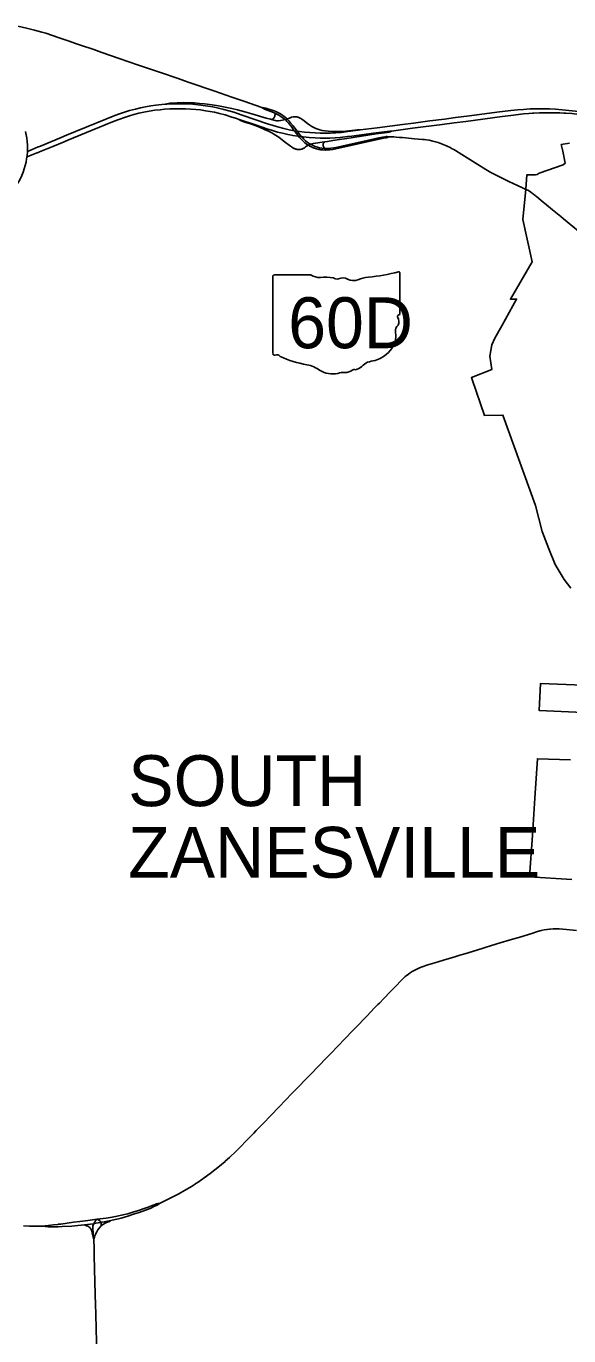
# Model space of a CAD drawing. Extents: x 2015843 to 2287843, y 623733 to 799733.
# Drawn here: x 2104493 to 2116443, y 678304 to 707117 of the extents above; entities that cross this region are included whole.
import ezdxf

# ---------------------------------------------------------------- set-up
doc = ezdxf.new("R2010")
doc.units = 0
for name, color, linetype in [('GM_X_Corporation', 7, 'Continuous'), ('GM_X_Corporation_Text', 7, 'Continuous'), ('GM_X_Interchange_Ramps', 7, 'Continuous'), ('GM_X_Interstate_Shield', 7, 'Continuous'), ('GM_X_State_Route', 7, 'Continuous'), ('GM_X_State_Shield', 7, 'Continuous'), ('GM_X_US_Route', 7, 'Continuous'), ('UT_P_Electric', 7, 'Continuous')]:
    doc.layers.add(name, color=color, linetype=linetype)

msp = doc.modelspace()

# ---------------------------------------------------------------- linework, layer by layer
at = {"layer": 'GM_X_Corporation'}
for points in [[(2116485, 694750), (2116340, 694942), (2116139, 695275), (2116001, 695619), (2115854, 695998), (2115707, 696572), (2114993, 698562), (2114585, 698555), (2114312, 699342), (2114299, 699384), (2114748, 699566), (2114702, 699857), (2114749, 700104), (2114817, 700252), (2114970, 700526), (2115293, 701114), (2115158, 701110), (2115639, 701929), (2115427, 702866), (2115498, 703530), (2115516, 703846), (2115709, 703850), (2115748, 703856), (2115791, 703880), (2116317, 704069), (2116362, 704101), (2116309, 704368), (2116276, 704512), (2116456, 704542)], [(2116759, 692016), (2115787, 692062), (2115818, 692654), (2117881, 692571)], [(2116508, 688344), (2115580, 688405), (2115645, 689311), (2115692, 690134), (2115750, 691001), (2116478, 690976)]]:
    msp.add_lwpolyline(points, dxfattribs=at)
at = {"layer": 'GM_X_Interchange_Ramps'}
for points in [[(2106137, 680715), (2106142, 680745), (2106142, 680774), (2106137, 680793), (2106134, 680800), (2106127, 680815), (2106120, 680825), (2106113, 680833), (2106106, 680841), (2106097, 680848), (2106083, 680856), (2106055, 680869)], [(2105778, 680744), (2105807, 680731), (2105822, 680727), (2105838, 680721), (2105854, 680714), (2105868, 680706), (2105882, 680696), (2105895, 680684), (2105906, 680672), (2105916, 680658), (2105924, 680643), (2105931, 680628), (2105939, 680606), (2105948, 680566), (2105981, 680412)]]:
    msp.add_lwpolyline(points, dxfattribs=at)
at = {"layer": 'GM_X_Interstate_Shield'}
msp.add_arc((2103013, 704433), 1509, 281.537, 14.1934, dxfattribs=at)
at = {"layer": 'GM_X_State_Route'}
msp.add_line((2114644, 686858), (2114694, 686874), dxfattribs=at)
for points in [[(2115340, 687070), (2115457, 687106), (2115630, 687158), (2115756, 687197), (2115836, 687219), (2115900, 687234), (2115965, 687245), (2116016, 687251)], [(2116016, 687251), (2116030, 687252), (2116096, 687257), (2116161, 687258), (2116227, 687255), (2116391, 687241), (2116538, 687226), (2116612, 687223)], [(2114694, 686874), (2114859, 686924), (2115206, 687029), (2115340, 687070)], [(2112843, 686206), (2112860, 686221), (2112911, 686262), (2112951, 686290), (2112993, 686317), (2113049, 686350), (2113108, 686379), (2113153, 686399), (2113215, 686422), (2113339, 686462), (2113496, 686511), (2113685, 686567), (2113810, 686605), (2113935, 686644), (2114045, 686676), (2114151, 686708), (2114419, 686789), (2114576, 686838), (2114644, 686858)], [(2112525, 685887), (2112529, 685891), (2112660, 686027), (2112720, 686088)], [(2112720, 686088), (2112763, 686132), (2112811, 686178), (2112843, 686206)], [(2112279, 685630), (2112364, 685720), (2112525, 685887)], [(2111164, 684479), (2111202, 684518), (2111511, 684835), (2111557, 684881), (2111646, 684978), (2111737, 685073), (2111999, 685343), (2112158, 685509), (2112239, 685590), (2112274, 685625), (2112279, 685630)], [(2110810, 684113), (2110871, 684177), (2111164, 684479)], [(2110465, 683757), (2110495, 683788), (2110643, 683941), (2110810, 684113)], [(2109558, 682818), (2109709, 682975), (2109880, 683151), (2110062, 683340), (2110347, 683635), (2110465, 683757)], [(2108878, 682144), (2108972, 682227), (2109115, 682363), (2109241, 682492), (2109310, 682562), (2109401, 682656), (2109489, 682747)], [(2109489, 682747), (2109504, 682762), (2109558, 682818)], [(2108194, 681629), (2108207, 681638), (2108303, 681701), (2108410, 681776), (2108543, 681872), (2108647, 681952), (2108749, 682035), (2108874, 682141), (2108878, 682144)], [(2107428, 681218), (2107577, 681288), (2107738, 681368), (2107854, 681429), (2107983, 681501), (2108096, 681568), (2108194, 681629)], [(2106361, 680842), (2106453, 680861), (2106524, 680878), (2106582, 680893), (2106735, 680939), (2106859, 680977), (2106983, 681019), (2107121, 681068), (2107223, 681108), (2107319, 681153), (2107362, 681171), (2107392, 681186), (2107409, 681197), (2107419, 681205), (2107428, 681218)], [(2105981, 680412), (2105970, 680546), (2105963, 680683), (2105964, 680718), (2105968, 680739), (2105974, 680757), (2105981, 680771), (2105987, 680784), (2105994, 680795), (2106003, 680808), (2106011, 680819), (2106020, 680831), (2106031, 680845), (2106055, 680869)], [(2105981, 680412), (2105991, 680452), (2105998, 680474), (2106009, 680505), (2106020, 680535), (2106033, 680566), (2106048, 680594), (2106074, 680636), (2106102, 680672), (2106137, 680715), (2106143, 680720), (2106151, 680726), (2106168, 680742), (2106195, 680761), (2106230, 680783), (2106260, 680796), (2106284, 680806), (2106328, 680820), (2106341, 680827), (2106361, 680842)], [(2106034, 678559), (2106031, 678679), (2106027, 678768), (2106025, 678810), (2106023, 678974), (2106009, 679483), (2106001, 679778), (2105994, 680064), (2105989, 680231), (2105981, 680412)], [(2105898, 675462), (2105899, 675476), (2105908, 675640), (2105914, 675738), (2105923, 675918), (2105923, 675922), (2105941, 676213), (2105943, 676250), (2105961, 676511), (2105964, 676556), (2105977, 676781), (2105995, 677092), (2106001, 677197), (2106029, 677688), (2106035, 677798), (2106042, 677937), (2106042, 677947), (2106044, 678063), (2106043, 678238), (2106038, 678401), (2106034, 678559)]]:
    msp.add_lwpolyline(points, dxfattribs=at)
at = {"layer": 'GM_X_State_Shield'}
for p, q in [((2109923, 701613), (2109923, 699912)), ((2110771, 701643), (2109951, 701643)), ((2112725, 700795), (2112725, 701685)), ((2112725, 700795), (2112725, 700795))]:
    msp.add_line(p, q, dxfattribs=at)
for centre, major_axis, start_param, end_param in [((2109955, 701617), (32.5, 0), 1.712693, 3.28349), ((2110967, 701840), (315, 0), 4.042523, 4.731795), ((2111071, 700688), (1130, 0), 1.404758, 1.657858), ((2112106, 701123), (598, 0), 1.699011, 2.107814), ((2111727, 703962), (2971, 0), 4.814394, 5.042369), ((2112694, 701688), (31.2, 0), 6.141152, 7.989035), ((2111328, 701626), (90.8, 0), 3.836095, 5.185415), ((2111461, 701429), (189, 0), 0.950623, 2.079405), ((2111705, 701699), (227, 0), 4.081561, 5.145723), ((2112718, 700729), (48.3, 0), 1.883978, 3.671073), ((2112692, 700791), (33.4, 0), 5.05454, 6.418171), ((2112837, 700422), (211, 0), 2.387724, 3.262537), ((2112411, 700617), (290, 0), 5.934695, 6.695948), ((2111893, 700309), (743, 0), 5.101752, 6.440018), ((2109956, 699908), (32.7, 0), 3.00124, 4.508301), ((2109961, 700082), (250, 0), 4.665946, 4.897461), ((2110012, 699814), (90.1, 0), 0.519207, 1.627899), ((2111149, 701342), (2146, 0), 4.195997, 4.488961), ((2110510, 699148), (671, 0), 0.823519, 1.323587), ((2111691, 699747), (240, 0), 4.937069, 5.64225), ((2112207, 699435), (407, 0), 1.647645, 2.488434), ((2111236, 699806), (426, 0), 4.026481, 4.996735), ((2111482, 699217), (350, 0), 1.495662, 1.94098), ((2111513, 699678), (227, 0), 4.691044, 5.507374), ((2111718, 699513), (63.9, 0), 1.147584, 2.315152)]:
    msp.add_ellipse(centre, major_axis=major_axis, ratio=0.8, start_param=start_param, end_param=end_param, dxfattribs=at)
at = {"layer": 'GM_X_US_Route'}
msp.add_line((2114644, 686858), (2114694, 686874), dxfattribs=at)
for points in [[(2104312, 707117), (2104500, 707075), (2104678, 707031), (2104836, 706987), (2104925, 706960), (2105219, 706862), (2105421, 706796), (2105605, 706729), (2105797, 706665), (2105850, 706647), (2105981, 706602), (2106163, 706539), (2106539, 706409), (2106969, 706262), (2107341, 706134), (2107451, 706096), (2107838, 705963), (2108060, 705887), (2108646, 705687), (2109022, 705558), (2109289, 705464), (2109682, 705329)], [(2109682, 705329), (2109718, 705304), (2109744, 705291), (2109879, 705243), (2109940, 705219), (2109984, 705199)], [(2109682, 705329), (2109734, 705323), (2109771, 705315), (2109958, 705251), (2109994, 705237)], [(2109984, 705199), (2109997, 705192), (2110029, 705176), (2110071, 705152), (2110112, 705124), (2110165, 705085), (2110173, 705079), (2110194, 705063), (2110217, 705042), (2110237, 705019), (2110274, 704978), (2110326, 704914), (2110390, 704827)], [(2109994, 705237), (2110004, 705233), (2110049, 705213), (2110092, 705189), (2110148, 705153), (2110178, 705131), (2110200, 705113), (2110219, 705097), (2110240, 705079), (2110251, 705067), (2110277, 705038), (2110310, 705000), (2110371, 704924), (2110458, 704808), (2110490, 704766), (2110531, 704715), (2110556, 704686), (2110575, 704665), (2110609, 704629), (2110646, 704596), (2110684, 704565), (2110725, 704537), (2110753, 704520), (2110768, 704512), (2110813, 704490), (2110859, 704471), (2110906, 704455), (2110954, 704443), (2111003, 704434), (2111052, 704429), (2111081, 704427), (2111102, 704427), (2111152, 704428), (2111201, 704432), (2111266, 704442), (2111347, 704457), (2111540, 704499), (2112005, 704604), (2112262, 704661), (2112343, 704677), (2112391, 704684), (2112417, 704686), (2112427, 704687), (2112435, 704688), (2112444, 704687), (2112452, 704686), (2112460, 704684), (2112469, 704681)], [(2110390, 704827), (2110397, 704818), (2110414, 704796), (2110473, 704717), (2110486, 704702)], [(2110486, 704702), (2110492, 704694), (2110514, 704667), (2110548, 704631), (2110595, 704586), (2110632, 704554), (2110670, 704524), (2110707, 704500), (2110719, 704494), (2110752, 704473), (2110774, 704462), (2110798, 704451), (2110819, 704442), (2110841, 704434), (2110865, 704425), (2110888, 704418), (2110913, 704412), (2110936, 704406), (2110959, 704401), (2110984, 704397), (2111033, 704393), (2111082, 704392), (2111095, 704392), (2111131, 704393), (2111179, 704397), (2111244, 704407), (2111341, 704425), (2111580, 704478), (2112029, 704579), (2112268, 704633), (2112365, 704653), (2112396, 704658), (2112420, 704663), (2112434, 704666), (2112446, 704668), (2112454, 704671), (2112458, 704674), (2112469, 704681)], [(2112469, 704681), (2112504, 704682), (2112551, 704682), (2112589, 704680), (2112640, 704677), (2112712, 704671), (2112780, 704665), (2112911, 704654), (2113044, 704642), (2113222, 704626), (2113268, 704621), (2113306, 704616), (2113368, 704606), (2113449, 704589), (2113508, 704573), (2113564, 704556), (2113601, 704543), (2113642, 704528), (2113712, 704499), (2113763, 704477), (2113828, 704445), (2113875, 704421), (2113909, 704401), (2113946, 704379), (2114086, 704293), (2114616, 703967), (2114729, 703901), (2114815, 703854), (2114917, 703802), (2115123, 703703), (2115316, 703612), (2115423, 703562), (2115469, 703541), (2115517, 703519)], [(2115517, 703519), (2115538, 703509), (2115580, 703485), (2115607, 703467), (2115645, 703437), (2115667, 703419), (2115704, 703389), (2115719, 703376), (2115732, 703367), (2115774, 703333), (2115887, 703237), (2115904, 703222), (2116083, 703077), (2116122, 703044), (2116267, 702926), (2116324, 702879), (2116410, 702809), (2116658, 702607)], [(2115340, 687070), (2115457, 687106), (2115630, 687158), (2115756, 687197), (2115836, 687219), (2115900, 687234), (2115965, 687245), (2116016, 687251)], [(2116016, 687251), (2116030, 687252), (2116096, 687257), (2116161, 687258), (2116227, 687255), (2116391, 687241), (2116538, 687226), (2116612, 687223)], [(2114694, 686874), (2114859, 686924), (2115206, 687029), (2115340, 687070)], [(2112843, 686206), (2112860, 686221), (2112911, 686262), (2112951, 686290), (2112993, 686317), (2113049, 686350), (2113108, 686379), (2113153, 686399), (2113215, 686422), (2113339, 686462), (2113496, 686511), (2113685, 686567), (2113810, 686605), (2113935, 686644), (2114045, 686676), (2114151, 686708), (2114419, 686789), (2114576, 686838), (2114644, 686858)], [(2112525, 685887), (2112529, 685891), (2112660, 686027), (2112720, 686088)], [(2112720, 686088), (2112763, 686132), (2112811, 686178), (2112843, 686206)], [(2112279, 685630), (2112364, 685720), (2112525, 685887)], [(2111164, 684479), (2111202, 684518), (2111511, 684835), (2111557, 684881), (2111646, 684978), (2111737, 685073), (2111999, 685343), (2112158, 685509), (2112239, 685590), (2112274, 685625), (2112279, 685630)], [(2110810, 684113), (2110871, 684177), (2111164, 684479)], [(2110465, 683757), (2110495, 683788), (2110643, 683941), (2110810, 684113)], [(2109558, 682818), (2109709, 682975), (2109880, 683151), (2110062, 683340), (2110347, 683635), (2110465, 683757)], [(2108878, 682144), (2108972, 682227), (2109115, 682363), (2109241, 682492), (2109310, 682562), (2109401, 682656), (2109489, 682747)], [(2109489, 682747), (2109504, 682762), (2109558, 682818)], [(2108194, 681629), (2108207, 681638), (2108303, 681701), (2108410, 681776), (2108543, 681872), (2108647, 681952), (2108749, 682035), (2108874, 682141), (2108878, 682144)], [(2107428, 681218), (2107577, 681288), (2107738, 681368), (2107854, 681429), (2107983, 681501), (2108096, 681568), (2108194, 681629)], [(2104840, 680714), (2104912, 680726), (2104981, 680733), (2105095, 680744), (2105190, 680755), (2105200, 680757), (2105257, 680763), (2105532, 680802), (2105678, 680820), (2105852, 680843), (2106055, 680869), (2106256, 680892), (2106384, 680913), (2106496, 680934), (2106623, 680962), (2106734, 680990), (2106845, 681022), (2106969, 681061), (2107093, 681104), (2107203, 681145), (2107270, 681172), (2107331, 681194), (2107356, 681204), (2107379, 681211), (2107401, 681216), (2107428, 681218)], [(2106361, 680842), (2106453, 680861), (2106524, 680878), (2106582, 680893), (2106735, 680939), (2106859, 680977), (2106983, 681019), (2107121, 681068), (2107223, 681108), (2107319, 681153), (2107362, 681171), (2107392, 681186), (2107409, 681197), (2107419, 681205), (2107428, 681218)], [(2104433, 680720), (2104564, 680716), (2104840, 680714)], [(2104840, 680714), (2104912, 680707), (2104975, 680704), (2105031, 680703), (2105158, 680704), (2105197, 680705), (2105288, 680709), (2105501, 680719), (2105631, 680729), (2105778, 680744), (2105907, 680762), (2105981, 680771), (2106020, 680779), (2106134, 680800), (2106157, 680804), (2106212, 680813), (2106361, 680842)]]:
    msp.add_lwpolyline(points, dxfattribs=at)
at = {"layer": 'UT_P_Electric'}
for points in [[(2105265, 704668), (2105382, 704716), (2106247, 705072), (2106445, 705151), (2106552, 705190), (2106661, 705226), (2106771, 705259), (2106898, 705293), (2107009, 705319), (2107122, 705342), (2107235, 705361), (2107348, 705377), (2107478, 705392), (2107555, 705398)], [(2110194, 705063), (2110135, 705049), (2110097, 705041), (2110053, 705037), (2110009, 705038), (2109974, 705044), (2109896, 705064), (2109872, 705070), (2109779, 705096), (2109465, 705191), (2109307, 705234), (2109149, 705276), (2109021, 705305), (2108877, 705335), (2108732, 705362), (2108586, 705384), (2108423, 705406), (2108309, 705418), (2108195, 705427), (2108080, 705433), (2107966, 705435), (2107815, 705433), (2107688, 705425), (2107657, 705421), (2107628, 705418), (2107595, 705410), (2107555, 705398)], [(2107555, 705398), (2107593, 705401), (2107707, 705407), (2107822, 705410), (2107936, 705410), (2108051, 705406), (2108165, 705399), (2108280, 705388), (2108393, 705375), (2108491, 705360), (2108603, 705340), (2108732, 705313), (2108843, 705286), (2108954, 705255), (2109063, 705222), (2109250, 705160), (2109809, 704969), (2109934, 704930), (2110060, 704893), (2110171, 704864), (2110284, 704839), (2110397, 704818), (2110458, 704808), (2110510, 704800), (2110624, 704786), (2110739, 704775), (2110854, 704768), (2110968, 704764), (2111083, 704763), (2111198, 704766), (2111313, 704772), (2111428, 704781), (2111575, 704797), (2111802, 704827), (2111851, 704833), (2112225, 704882), (2112778, 704954), (2113022, 704985), (2113380, 705031), (2113705, 705074), (2113949, 705105), (2114258, 705145), (2114860, 705224), (2115169, 705261), (2115316, 705277), (2115447, 705287), (2115594, 705295), (2115688, 705298)], [(2105328, 704575), (2105411, 704609), (2106230, 704947), (2106428, 705027), (2106535, 705067), (2106659, 705110), (2106769, 705145), (2106864, 705172), (2106975, 705200), (2107088, 705224), (2107201, 705245), (2107330, 705266), (2107444, 705280), (2107542, 705289), (2107657, 705297), (2107772, 705301), (2107871, 705302), (2108002, 705299), (2108117, 705293), (2108231, 705284), (2108329, 705273), (2108443, 705257), (2108540, 705241), (2108637, 705222), (2108749, 705196), (2108876, 705163), (2109002, 705126), (2109127, 705086), (2109165, 705073)], [(2109165, 705073), (2109191, 705055), (2109212, 705045), (2109307, 705007), (2109431, 704965), (2109555, 704921), (2109647, 704885), (2109738, 704847), (2109827, 704805), (2109901, 704768), (2109944, 704744), (2109986, 704719), (2110054, 704672), (2110172, 704583), (2110316, 704474), (2110357, 704446), (2110386, 704429), (2110401, 704423), (2110432, 704412), (2110448, 704408), (2110464, 704406), (2110480, 704404), (2110497, 704404), (2110513, 704405), (2110530, 704407), (2110546, 704410), (2110562, 704414), (2110577, 704419), (2110592, 704425), (2110621, 704441), (2110647, 704461), (2110667, 704476), (2110679, 704484), (2110691, 704491), (2110707, 704500)], [(2109165, 705073), (2109562, 704938), (2109795, 704859), (2109920, 704819), (2110030, 704788), (2110141, 704760), (2110253, 704735), (2110299, 704727)], [(2109984, 705199), (2109975, 705174), (2109971, 705154), (2109968, 705137), (2109962, 705122), (2109955, 705106), (2109945, 705093), (2109929, 705080), (2109911, 705071), (2109896, 705064)], [(2111851, 704833), (2111813, 704838), (2111790, 704836), (2111728, 704830), (2111598, 704817), (2111469, 704803), (2111387, 704798), (2111305, 704797), (2111223, 704800), (2111141, 704806), (2111076, 704814), (2111011, 704825), (2110963, 704836), (2110916, 704849), (2110870, 704867), (2110825, 704887), (2110782, 704911), (2110741, 704938), (2110688, 704977), (2110584, 705057), (2110543, 705085), (2110515, 705101), (2110500, 705108), (2110484, 705113), (2110469, 705118), (2110453, 705122), (2110437, 705124), (2110420, 705125), (2110404, 705126), (2110387, 705124), (2110371, 705122), (2110339, 705114), (2110308, 705104), (2110290, 705096), (2110240, 705079), (2110194, 705063)], [(2111662, 704698), (2112142, 704760), (2112500, 704805), (2112537, 704810), (2113004, 704872), (2113655, 704956), (2113915, 704989), (2114176, 705022), (2114972, 705127), (2115167, 705152), (2115444, 705185), (2115559, 705196), (2115642, 705202)], [(2115642, 705202), (2115673, 705205), (2115799, 705211)], [(2115688, 705298), (2115725, 705299), (2115785, 705299), (2115856, 705299), (2116020, 705295), (2116151, 705289), (2116298, 705278), (2116445, 705264), (2116591, 705246), (2116737, 705224), (2116866, 705202), (2117177, 705139), (2117321, 705104), (2117343, 705098), (2117409, 705081), (2117536, 705047), (2117654, 705013)], [(2115799, 705211), (2115805, 705211), (2115887, 705213), (2115952, 705214), (2116100, 705214), (2116121, 705213)], [(2116121, 705213), (2116248, 705210), (2116332, 705206)], [(2116332, 705206), (2116379, 705203), (2116510, 705193), (2116673, 705176), (2116820, 705157), (2116949, 705137), (2117063, 705117), (2117164, 705096)], [(2110707, 704500), (2110753, 704520), (2110817, 704536), (2111063, 704573), (2111131, 704582), (2111250, 704601), (2111396, 704622), (2111557, 704648), (2112198, 704745), (2112440, 704781), (2112484, 704787), (2112509, 704796), (2112537, 704810)], [(2104761, 704460), (2104766, 704462), (2104806, 704479), (2105265, 704668)], [(2104761, 704341), (2104790, 704353), (2105078, 704472), (2105328, 704575)], [(2110299, 704727), (2110366, 704714), (2110479, 704696), (2110492, 704694), (2110556, 704686), (2110593, 704681), (2110723, 704668), (2110854, 704659), (2110968, 704654), (2111067, 704653), (2111181, 704655), (2111296, 704660), (2111410, 704669), (2111573, 704687), (2111662, 704698)], [(2111081, 704427), (2111058, 704445), (2111047, 704457), (2111038, 704470), (2111032, 704485), (2111030, 704501), (2111030, 704517), (2111035, 704533), (2111047, 704553), (2111063, 704573)], [(2104510, 704242), (2104531, 704250), (2104714, 704322), (2104761, 704341)], [(2104521, 704363), (2104624, 704404), (2104761, 704460)]]:
    msp.add_lwpolyline(points, dxfattribs=at)

# ---------------------------------------------------------------- texts
at = {"layer": 'GM_X_Corporation_Text'}
for s, p in [('SOUTH', (2106741, 689957)), ('ZANESVILLE', (2106741, 688381))]:
    msp.add_text(s, height=1120, rotation=0, dxfattribs=at).set_placement(p)
at = {"layer": 'GM_X_State_Shield'}
msp.add_text('60D', height=1120.7, dxfattribs=at).set_placement((2110263, 700032))

doc.saveas('drawing.dxf')
